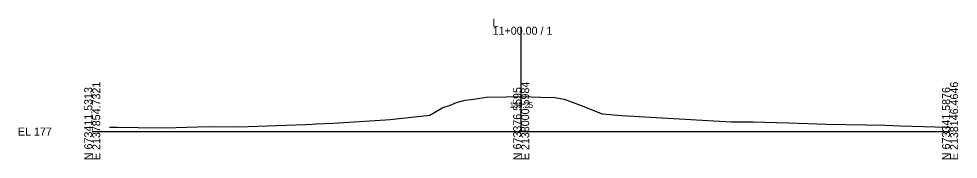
# Model space of a CAD drawing. Extents: x -26 to 5503, y -10 to 7033.
# Drawn here: x -25.7 to 302.8, y 1990.3 to 2039.6 of the extents above; entities that cross this region are included whole.
import ezdxf

# ---------------------------------------------------------------- set-up
doc = ezdxf.new("R2010")
doc.units = 0
for name, color, linetype in [('Exist Cross Section Cell', 7, 'Continuous'), ('Exist XS Center Line Elevation Label', 7, 'Continuous'), ('Exist XS Ground Line', 7, 'Continuous')]:
    doc.layers.add(name, color=color, linetype=linetype)

msp = doc.modelspace()

# ---------------------------------------------------------------- linework, layer by layer
at = {"layer": 'Exist Cross Section Cell'}
for p, q in [((150, 2000), (150, 2036.75)), ((0, 2000), (150, 2000)), ((150, 2000), (300, 2000))]:
    msp.add_line(p, q, dxfattribs=at)
at = {"layer": 'Exist XS Ground Line'}
for p, q in [((127.33, 2010.15), (130.37, 2011)), ((130.37, 2011), (132.5, 2011.22)), ((132.5, 2011.22), (137.88, 2012.04)), ((137.88, 2012.04), (144.78, 2012.13)), ((144.78, 2012.13), (150.14, 2012.25)), ((150.14, 2012.25), (156.92, 2012.05)), ((156.92, 2012.05), (161.76, 2011.95)), ((161.76, 2011.95), (165.07, 2011.42)), ((165.07, 2011.42), (171.03, 2009.16)), ((118.03, 2005.8), (122.61, 2008.41)), ((122.61, 2008.41), (124.92, 2009.19)), ((124.92, 2009.19), (127.33, 2010.15)), ((171.03, 2009.16), (178.32, 2006.27)), ((84.25, 2003.01), (102.56, 2004.14)), ((102.56, 2004.14), (104.23, 2004.24)), ((104.23, 2004.24), (118.03, 2005.8)), ((178.32, 2006.27), (185.21, 2005.63)), ((185.21, 2005.63), (223.44, 2003.45)), ((5.98, 2001.54), (8.78, 2001.55)), ((8.78, 2001.55), (16.07, 2001.45)), ((16.07, 2001.45), (25.44, 2001.34)), ((25.44, 2001.34), (40.71, 2001.74)), ((40.71, 2001.74), (51.15, 2001.66)), ((51.15, 2001.66), (74.52, 2002.52)), ((74.52, 2002.52), (76.85, 2002.65)), ((76.85, 2002.65), (78.28, 2002.74)), ((78.28, 2002.74), (84.25, 2003.01)), ((223.44, 2003.45), (231.1, 2003.47)), ((231.1, 2003.47), (243.6, 2003.06)), ((243.6, 2003.06), (256.81, 2002.63)), ((256.81, 2002.63), (277.42, 2002.24)), ((277.42, 2002.24), (282.52, 2002.02)), ((282.52, 2002.02), (298.71, 2001.61)), ((298.71, 2001.61), (300, 2001.57))]:
    msp.add_line(p, q, dxfattribs=at)

# ---------------------------------------------------------------- texts
at = {"layer": 'Exist Cross Section Cell'}
for s, p in [('L', (140, 2036.75)), ('11+00.00 / 1', (140, 2033.95)), ('EL 177', (-26, 1998.6))]:
    msp.add_text(s, height=2.8, dxfattribs=at).set_placement(p)
for s, p in [('E 2137854.7321', (2.8, 1990)), ('E 2138000.5984', (152.8, 1990)), ('E 2138146.4646', (302.8, 1990)), ('N 673411.5313', (0, 1990)), ('N 673376.5595', (150, 1990)), ('N 673341.5876', (300, 1990))]:
    msp.add_text(s, height=2.8, rotation=90, dxfattribs=at).set_placement(p)
at = {"layer": 'Exist XS Center Line Elevation Label'}
msp.add_text('189.25', height=2, dxfattribs=at).set_placement((145.98, 2008.25))

doc.saveas('drawing.dxf')
